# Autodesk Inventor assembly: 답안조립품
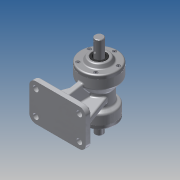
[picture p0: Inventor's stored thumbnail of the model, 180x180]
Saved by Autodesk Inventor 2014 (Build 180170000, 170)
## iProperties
Created: 2015-08
Part Number: 답안조립품
Document SubType Name: Assembly
Designer: SDA21
Author: SDA21
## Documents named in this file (10)
- C:\Users\SDA21\Desktop\450805V1006\답안조립품.iam
- C:\Users\SDA21\Desktop\450805V1006\본체.ipt
- C:\Users\SDA21\Desktop\450805V1006\베어링 6203.ipt
- C:\Users\SDA21\Desktop\450805V1006\베어링 6205.ipt
- C:\Users\SDA21\Desktop\450805V1006\축.ipt
- C:\Users\SDA21\Desktop\450805V1006\뒤커버.ipt
- C:\Users\SDA21\Desktop\450805V1006\앞커버.ipt
- C:\Users\SDA21\Desktop\450805V1006\오일실 .ipt
- 오일실 .ipt
- C:\Users\SDA21\Desktop\450805V1006\M4x0.5.ipt
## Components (10 placed, 1 different names)
1. M4x0.5:2
2. M4x0.5:3
3. M4x0.5:4
4. M4x0.5:5
5. M4x0.5:6
6. M4x0.5:1
7. M4x0.5:7
8. M4x0.5:8
9. M4x0.5:9
10. M4x0.5:10
